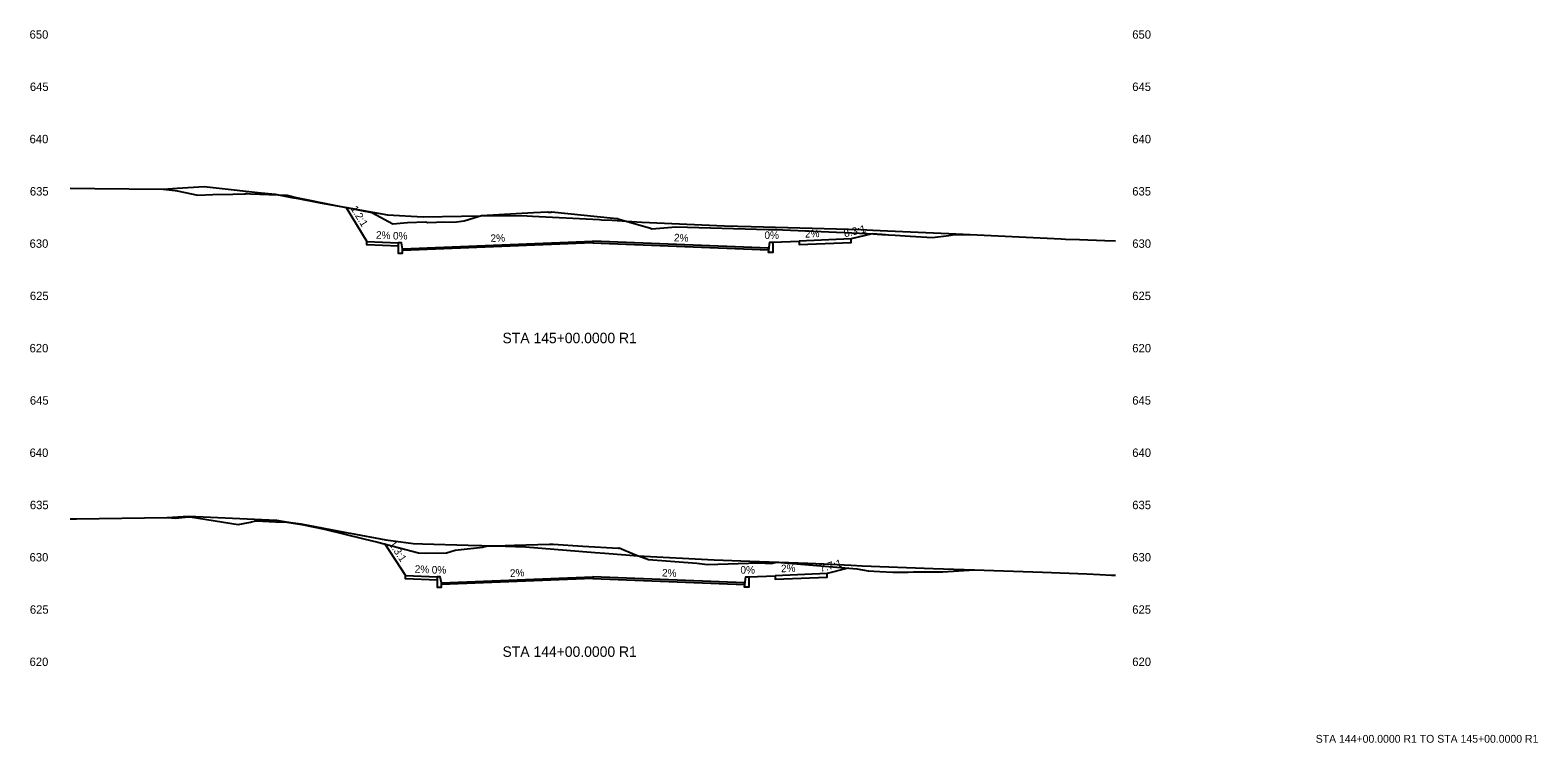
# Model space of a CAD drawing. Extents: x 12 to 301, y 16 to 1707.
# Drawn here: x 12.4 to 300.8, y 915.9 to 1052.2 of the extents above; entities that cross this region are included whole.
import ezdxf

# ---------------------------------------------------------------- set-up
doc = ezdxf.new("R2010")
doc.units = 0
for name, color, linetype in [('BORD_text_large_2', 7, 'Continuous'), ('Default', 7, 'Continuous'), ('Draft_XS_Point_Label_Indicator', 7, 'Continuous'), ('Draft_XS_Text', 7, 'Continuous'), ('Grade_Veg_Grass', 7, 'Continuous'), ('P_XS_Sections', 7, 'Continuous'), ('Road_Curb', 7, 'Continuous'), ('Road_Pave_Asphalt', 7, 'Continuous'), ('Road_Sidewalk', 7, 'Continuous'), ('Terrain_Exterior', 7, 'Continuous')]:
    doc.layers.add(name, color=color, linetype=linetype)

msp = doc.modelspace()

# ---------------------------------------------------------------- linework, layer by layer
at = {"layer": 'Default'}
for points in [[(20, 1021.99), (24.74, 1021.97), (37.79, 1021.84), (40.13, 1021.57), (40.49, 1021.5), (44.47, 1020.69), (47.32, 1020.78), (51.16, 1020.89), (53.38, 1020.95), (53.53, 1020.95), (53.57, 1020.95), (53.63, 1020.96), (53.84, 1020.96), (53.94, 1020.97), (54.52, 1020.93), (61.52, 1020.64), (63.25, 1020.19), (70.86, 1018.71), (77.71, 1017.33), (81.75, 1015.19), (84.58, 1015.43), (88.06, 1015.58), (88.38, 1015.46), (90.1, 1015.52), (93.91, 1015.59), (95.42, 1015.77), (95.61, 1015.82), (98.75, 1016.76), (108.68, 1017.38), (111.43, 1017.45), (111.52, 1017.43), (112.02, 1017.43), (112.09, 1017.45), (123.95, 1016.26), (124.77, 1016.22), (125.07, 1016.07), (131.03, 1014.34), (131.29, 1014.24), (135.89, 1014.59), (153.59, 1014.13), (155.14, 1014.07), (156.4, 1014.04), (172.49, 1013.34), (173.68, 1013.24), (174.33, 1013.24), (174.37, 1013.24), (174.44, 1013.23), (174.49, 1013.23), (174.55, 1013.23), (174.66, 1013.22), (174.78, 1013.21), (174.9, 1013.2), (175.04, 1013.19), (175.17, 1013.18), (175.28, 1013.18), (175.34, 1013.17), (175.4, 1013.17), (175.61, 1013.16), (176.01, 1013.13), (176.61, 1013.09), (177.87, 1013.01), (180.76, 1012.82), (185.03, 1012.54), (188.13, 1012.97), (189.22, 1013.12), (192.21, 1013.12), (209.61, 1012.32), (210.43, 1012.28), (213.14, 1012.17), (218, 1012), (220, 1011.93)], [(20, 958.74), (21.21, 958.74), (38.59, 958.98), (40.19, 958.91), (42.69, 959.12), (43.01, 959.15), (52.14, 957.69), (54.52, 958.13), (54.73, 958.17), (55.31, 958.28), (55.67, 958.34), (55.7, 958.35), (59.33, 958.19), (61.49, 958.1), (64.34, 957.65), (68.71, 956.78), (76.22, 954.9), (78.86, 954.3), (86.7, 952.27), (87.92, 952.18), (92.02, 952.24), (93.67, 952.76), (98.91, 953.36), (99.53, 953.53), (99.65, 953.53), (105.01, 953.73), (111.71, 953.91), (112.11, 953.91), (112.43, 953.91), (118.13, 953.51), (124.91, 953.15), (125.05, 953.19), (128.05, 951.96), (130.65, 950.95), (139.92, 950.24), (141.97, 950.04), (151.78, 950.32), (154.16, 950.23), (155.23, 950.47), (170.51, 949.18), (172.69, 948.79), (174.94, 948.67), (177.41, 948.57), (177.61, 948.57), (177.66, 948.57), (177.71, 948.57), (178.01, 948.57), (178.37, 948.57), (178.47, 948.57), (178.55, 948.57), (178.58, 948.58), (179.1, 948.58), (179.75, 948.58), (179.91, 948.58), (179.92, 948.58), (180.01, 948.58), (180.13, 948.58), (180.32, 948.58), (181.34, 948.59), (181.46, 948.59), (183.13, 948.6), (184.11, 948.6), (185.43, 948.61), (185.73, 948.61), (186.99, 948.63), (193.03, 949.02), (206.05, 948.56), (214.5, 948.24), (217.02, 948.11), (219.24, 948), (220, 947.96)]]:
    msp.add_lwpolyline(points, dxfattribs=at)
at = {"layer": 'Grade_Veg_Grass'}
for points in [[(72.8, 1018.32), (72.8, 1018.32), (76.8, 1011.82)], [(173.47, 1013.25), (173.47, 1013.25), (169.47, 1012.29)], [(154.47, 1011.69), (159.47, 1011.89)], [(80.21, 953.95), (80.21, 953.95), (84.21, 947.92)], [(168.88, 949.32), (168.88, 949.32), (164.88, 948.27)], [(149.88, 947.67), (154.88, 947.87)]]:
    msp.add_lwpolyline(points, dxfattribs=at)
at = {"layer": 'Road_Curb'}
for points in [[(82.8, 1011.58), (82.8, 1009.58), (83.63, 1009.58), (83.63, 1010.41), (83.4, 1011.58), (82.8, 1011.58)], [(154.47, 1011.69), (154.47, 1009.69), (153.63, 1009.69), (153.86, 1011.69), (154.47, 1011.69)], [(90.21, 947.68), (90.21, 945.68), (91.04, 945.68), (91.04, 946.51), (90.81, 947.68), (90.21, 947.68)], [(149.88, 947.67), (149.88, 945.67), (149.05, 945.67), (149.27, 947.67), (149.88, 947.67)]]:
    msp.add_lwpolyline(points, dxfattribs=at)
at = {"layer": 'Road_Pave_Asphalt'}
for points in [[(83.63, 1010.41), (120, 1011.87), (120, 1011.87), (120, 1011.53), (83.63, 1010.08), (83.63, 1010.08), (83.63, 1010.41), (83.63, 1010.41), (83.63, 1010.41)], [(153.63, 1010.52), (120, 1011.87), (120, 1011.87), (120, 1011.53), (153.63, 1010.19), (153.63, 1010.19), (153.63, 1010.52), (153.63, 1010.52), (153.63, 1010.52)], [(91.04, 946.51), (120, 947.67), (120, 947.67), (120, 947.33), (91.04, 946.18), (91.04, 946.18), (91.04, 946.51), (91.04, 946.51), (91.04, 946.51)], [(149.05, 946.51), (120, 947.67), (120, 947.67), (120, 947.33), (149.05, 946.17), (149.05, 946.17), (149.05, 946.51), (149.05, 946.51), (149.05, 946.51)]]:
    msp.add_lwpolyline(points, dxfattribs=at)
at = {"layer": 'Road_Sidewalk'}
for points in [[(82.8, 1011.58), (82.8, 1010.91), (76.8, 1011.15), (76.8, 1011.82), (82.8, 1011.58)], [(159.47, 1011.89), (159.47, 1011.22), (169.47, 1011.62), (169.47, 1012.29), (159.47, 1011.89)], [(90.21, 947.68), (90.21, 947.01), (84.21, 947.25), (84.21, 947.92), (90.21, 947.68)], [(154.88, 947.87), (154.88, 947.21), (164.88, 947.61), (164.88, 948.27), (154.88, 947.87)]]:
    msp.add_lwpolyline(points, dxfattribs=at)
at = {"layer": 'Terrain_Exterior'}
for points in [[(20, 1021.99), (24.74, 1021.97), (37.79, 1021.84), (40.49, 1022), (45.68, 1022.31), (48.55, 1022), (55.94, 1021.2), (59.27, 1020.84), (62.41, 1020.24), (63.66, 1020), (66.61, 1019.44), (67.84, 1019.22), (74.72, 1018), (75.38, 1017.88), (80.75, 1016.93), (87.54, 1016.52), (102.22, 1016.8), (107.46, 1016.7), (108.48, 1016.68), (121.3, 1016), (121.68, 1015.98), (123.7, 1015.87), (129.41, 1015.51), (145.18, 1014.78), (150.34, 1014.65), (166.65, 1014.23), (166.67, 1014.23), (171.28, 1014.1), (173.56, 1014), (176.41, 1013.87), (188.13, 1013.35), (192.21, 1013.12), (209.61, 1012.32), (210.43, 1012.28), (213.14, 1012.17), (218, 1012), (220, 1011.93)], [(20, 958.74), (21.21, 958.74), (38.59, 958.98), (42.69, 959.28), (59.52, 958.5), (60.58, 958.33), (62.68, 958), (64.17, 957.77), (72.82, 956.15), (73.61, 956), (80.45, 954.72), (85.64, 954.06), (87.43, 954), (96.14, 953.73), (101.39, 953.56), (107.12, 953.37), (120.45, 952.34), (122.32, 952.2), (124.65, 952), (126.34, 951.85), (128.6, 951.66), (143.25, 950.88), (150.07, 950.68), (161.13, 950.24), (164.19, 950.12), (166.79, 950), (169.47, 949.88), (171.55, 949.78), (185.12, 949.25), (193.03, 949.02), (206.05, 948.56), (214.5, 948.24), (217.02, 948.11), (219.24, 948), (220, 947.96)]]:
    msp.add_lwpolyline(points, dxfattribs=at)

# ---------------------------------------------------------------- texts
at = {"layer": 'BORD_text_large_2'}
msp.add_text('STA 144+00.0000 R1 TO STA 145+00.0000 R1', height=1.5, dxfattribs=at).set_placement((258.32, 915.92))
at = {"layer": 'Draft_XS_Point_Label_Indicator'}
for p in [(72.79, 1018.31), (173.46, 1013.24), (76.79, 1011.81), (82.79, 1011.57), (83.39, 1011.57), (83.62, 1010.4), (119.99, 1011.86), (119.99, 1011.86), (153.62, 1010.51), (153.85, 1011.68), (154.46, 1011.68), (159.46, 1011.88), (169.46, 1012.28), (80.2, 953.94), (168.87, 949.3), (84.2, 947.9), (90.2, 947.66), (90.8, 947.66), (91.03, 946.5), (119.99, 947.66), (119.99, 947.66), (149.03, 946.49), (149.26, 947.66), (149.87, 947.66), (154.87, 947.86), (164.87, 948.26)]:
    msp.add_text('X', height=0.024, dxfattribs=at).set_placement(p)
at = {"layer": 'Draft_XS_Text'}
for s, height, p in [('650', 1.608, (12.26, 1050.6)), ('650', 1.608, (223.22, 1050.6)), ('645', 1.608, (12.32, 1040.6)), ('645', 1.608, (223.22, 1040.6)), ('640', 1.608, (12.26, 1030.6)), ('640', 1.608, (223.22, 1030.6)), ('635', 1.608, (12.32, 1020.6)), ('635', 1.608, (223.22, 1020.6)), ('630', 1.608, (12.26, 1010.6)), ('630', 1.608, (223.22, 1010.6)), ('625', 1.608, (12.32, 1000.6)), ('625', 1.608, (223.22, 1000.6)), ('STA 145+00.0000 R1', 1.992, (102.74, 992.35)), ('620', 1.608, (12.26, 990.6)), ('620', 1.608, (223.22, 990.6)), ('645', 1.608, (12.32, 980.6)), ('645', 1.608, (223.22, 980.6)), ('640', 1.608, (12.26, 970.6)), ('640', 1.608, (223.22, 970.6)), ('635', 1.608, (12.32, 960.6)), ('635', 1.608, (223.22, 960.6)), ('630', 1.608, (12.26, 950.6)), ('630', 1.608, (223.22, 950.6)), ('625', 1.608, (12.32, 940.6)), ('625', 1.608, (223.22, 940.6)), ('620', 1.608, (12.26, 930.6)), ('STA 144+00.0000 R1', 1.992, (102.74, 932.35)), ('620', 1.608, (223.22, 930.6))]:
    msp.add_text(s, height=height, dxfattribs=at).set_placement(p)
for s, rotation, p in [('1.2:1', 301.6073, (73.63, 1018.11)), ('1.2:1', 301.6073, (73.63, 1018.11)), ('1.2:1', 301.6073, (73.63, 1018.11)), ('2%', 357.7094, (78.51, 1012.35)), ('2%', 357.7094, (78.51, 1012.35)), ('2%', 357.7094, (78.51, 1012.35)), ('0%', 0, (81.79, 1012.18)), ('0%', 0, (81.79, 1012.18)), ('0%', 0, (81.79, 1012.18)), ('2%', 2.2906, (100.48, 1011.69)), ('2%', 2.2906, (100.48, 1011.69)), ('2%', 2.2906, (100.48, 1011.69)), ('2%', 357.7094, (135.53, 1011.85)), ('2%', 357.7094, (135.53, 1011.85)), ('2%', 357.7094, (135.53, 1011.85)), ('0%', 0, (152.85, 1012.29)), ('0%', 0, (152.85, 1012.29)), ('0%', 0, (152.85, 1012.29)), ('2%', 2.2906, (160.63, 1012.54)), ('2%', 2.2906, (160.63, 1012.54)), ('2%', 2.2906, (160.63, 1012.54)), ('8.3:1', 13.5608, (168.22, 1012.6)), ('8.3:1', 13.5608, (168.22, 1012.6)), ('8.3:1', 13.5608, (168.22, 1012.6)), ('1.3:1', 303.5523, (80.94, 953.93)), ('1.3:1', 303.5523, (80.94, 953.93)), ('1.3:1', 303.5523, (80.94, 953.93)), ('2%', 357.7094, (85.92, 948.45)), ('2%', 357.7094, (85.92, 948.45)), ('2%', 357.7094, (85.92, 948.45)), ('0%', 360, (89.2, 948.28)), ('0%', 360, (89.2, 948.28)), ('0%', 360, (89.2, 948.28)), ('2%', 2.2906, (104.18, 947.64)), ('2%', 2.2906, (104.18, 947.64)), ('2%', 2.2906, (104.18, 947.64)), ('2%', 357.7094, (133.23, 947.74)), ('2%', 357.7094, (133.23, 947.74)), ('2%', 357.7094, (133.23, 947.74)), ('0%', 0, (148.26, 948.27)), ('0%', 0, (148.26, 948.27)), ('0%', 0, (148.26, 948.27)), ('2%', 2.2906, (156.04, 948.52)), ('2%', 2.2906, (156.04, 948.52)), ('2%', 2.2906, (156.04, 948.52)), ('7.7:1', 14.6255, (163.63, 948.57)), ('7.7:1', 14.6255, (163.63, 948.57)), ('7.7:1', 14.6255, (163.63, 948.57))]:
    msp.add_text(s, height=1.44, rotation=rotation, dxfattribs=at).set_placement(p)
at = {"layer": 'P_XS_Sections'}
for p in [(20, 990), (20, 930)]:
    msp.add_text('-', height=0.0001, dxfattribs=at).set_placement(p)

doc.saveas('drawing.dxf')
